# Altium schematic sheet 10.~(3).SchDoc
size 420 x 297 mm
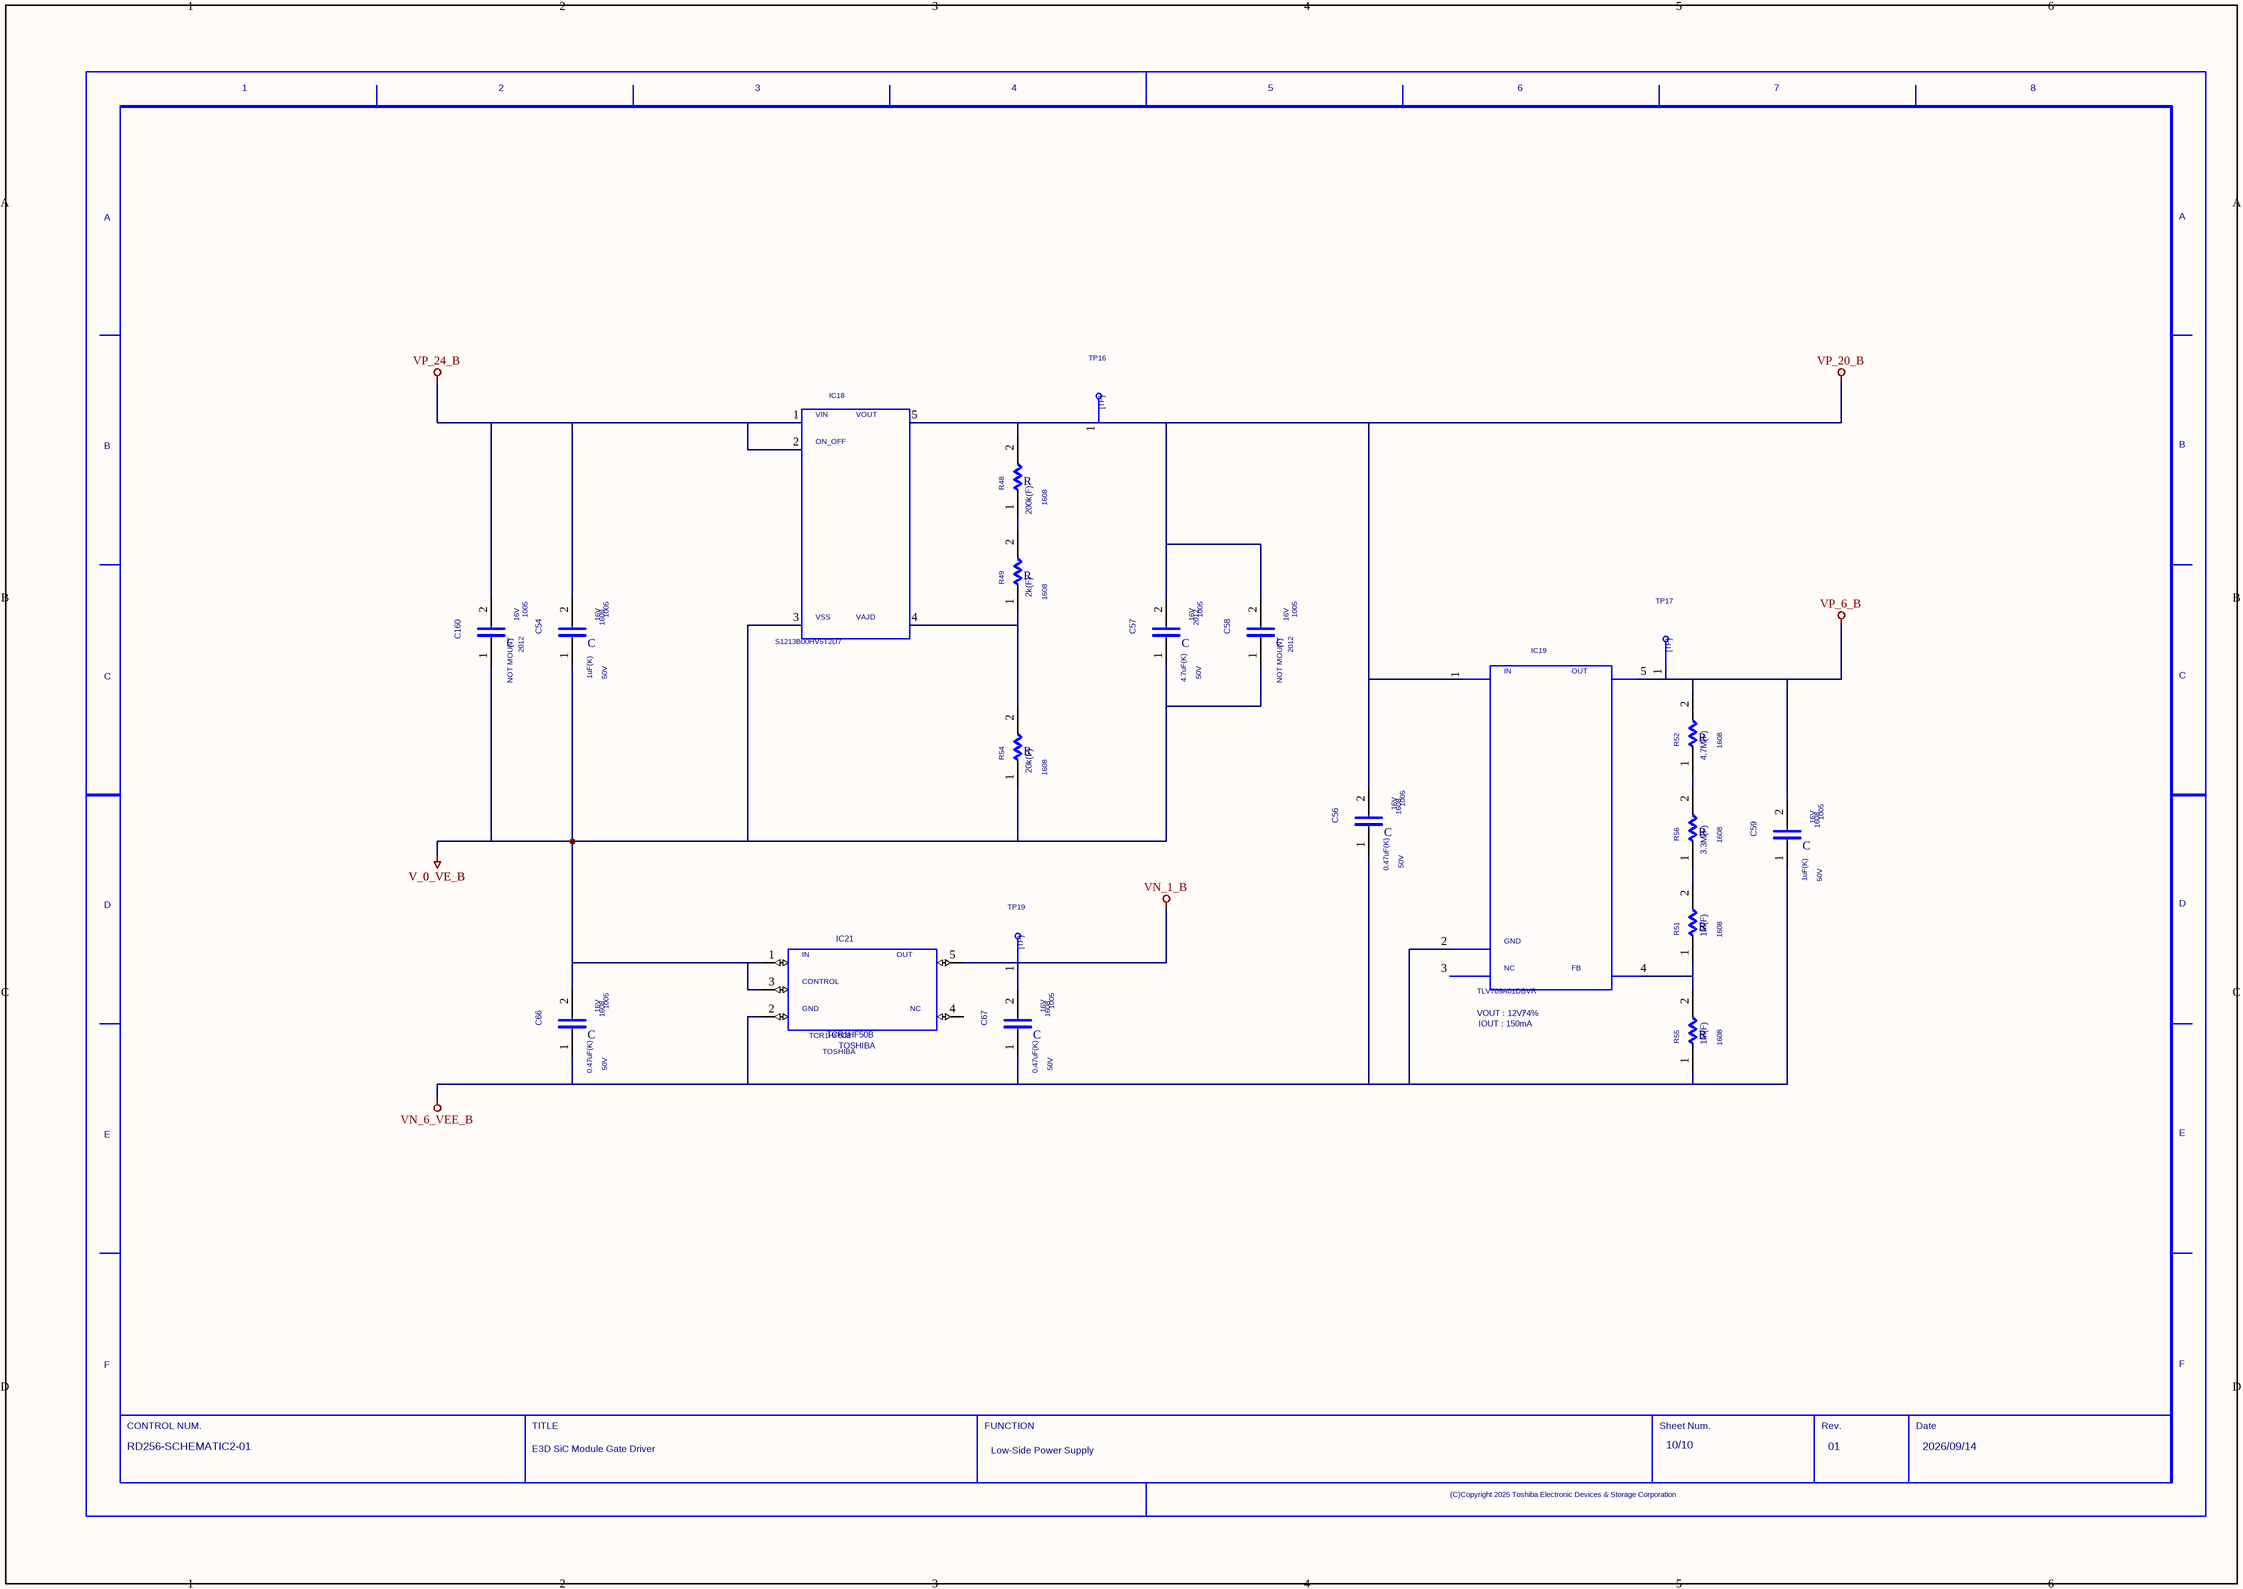
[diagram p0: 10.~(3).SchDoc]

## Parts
C54  VOLTAGE: 16V  CODE: 1005  VAL1: 1uF(K)  VAL2: 50V  SIZECODESMD: 1608  (hidden comment: C)
C56  VOLTAGE: 16V  CODE: 1005  VAL1: 0.47uF(K)  VAL2: 50V  SIZECODESMD: 1608  (hidden comment: C)
C57  VOLTAGE: 16V  CODE: 1005  VAL1: 4.7uF(K)  VAL2: 50V  SIZECODESMD: 2012  (hidden comment: C)
C58  VOLTAGE: 16V  CODE: 1005  SIZECODESMD: 2012  NOTMOUNT: NOT MOUNT  (hidden comment: C)
C59  VOLTAGE: 16V  CODE: 1005  VAL1: 1uF(K)  VAL2: 50V  SIZECODESMD: 1608  (hidden comment: C)
C66  VOLTAGE: 16V  CODE: 1005  VAL1: 0.47uF(K)  VAL2: 50V  SIZECODESMD: 1608  (hidden comment: C)
C67  VOLTAGE: 16V  CODE: 1005  VAL1: 0.47uF(K)  VAL2: 50V  SIZECODESMD: 1608  (hidden comment: C)
C160  VOLTAGE: 16V  CODE: 1005  SIZECODESMD: 2012  NOTMOUNT: NOT MOUNT  (hidden comment: C)
IC18  S1213B00HV5T2U7
IC19  CLASS: IOUT : 150mA  NC: VOUT : 12Vｱ4%  VAL3: TLV709A01DBVR  (hidden comment: TLV709)
IC21  TCR1HF50B  VENDOR: TOSHIBA
R48  VAL1: 200k(F)  SIZECODESMD: 1608  (hidden comment: R)
R49  VAL1: 2k(F)  SIZECODESMD: 1608  (hidden comment: R)
R51  VAL1: 1M(F)  SIZECODESMD: 1608  (hidden comment: R)
R52  VAL1: 4.7M(F)  SIZECODESMD: 1608  (hidden comment: R)
R54  VAL1: 20k(F)  SIZECODESMD: 1608  (hidden comment: R)
R55  VAL1: 1M(F)  SIZECODESMD: 1608  (hidden comment: R)
R56  VAL1: 3.3M(F)  SIZECODESMD: 1608  (hidden comment: R)
TP16  TP  (value not drawn)
TP17  TP  (value not drawn)
TP19  TP  (value not drawn)
U?  REVISION: 01  SHEETNUMBER: 10/10  FUNCTION: Low-Side Power Supply  TITLE: E3D SiC Module Gate Driver  DRAWINGNUMBER: RD256-SCHEMATIC2-01  DATE: 2026/09/14  (hidden comment: WAKU_DEF100)

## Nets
V_0_VE_B: C54.1 C57.1 C58.1 C66.2 C160.1 IC18.3 IC21.1 IC21.3 R54.1
VN_1_B: C67.2 IC21.5 TP19.1
VN_6_VEE_B: C56.1 C59.1 C66.1 C67.1 IC19.2 IC21.2 R55.1
VP_6_B: C59.2 IC19.5 R52.2 TP17.1
VP_20_B: C56.2 C57.2 C58.2 IC18.5 IC19.1 R48.2 TP16.1
VP_24_B: C54.2 C160.2 IC18.1 IC18.2
SIG0101: IC18.4 R49.1 R54.2
SIG0102: R52.1 R56.2
SIG0103: IC19.4 R51.1 R55.2
SIG0104: R48.1 R49.2
SIG0105: R51.2 R56.1

Not connected (* = marked no-connect by the designer): IC19 3; IC21 4

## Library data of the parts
C54 C56-C59 C66 C67 C160 = C: ORIGINALSYMBOLORIGIN: (0,0); VC2: 0; PSPICETEMPLATE: C^@REFDES %1 %2 ?TOLERANCE¦C^@REFDES¦ @VALUE ?IC/IC=@IC/ TC=@TC1,@TC2 ?TOLERANCE¦\n.model C^@REFDES CAP C=1 DEV=@TOLERANCE% TC1=@TC1 TC2=@TC2 VC1=@VC1 VC2=@VC2¦; SAVECOUNT: 2; UPDATETIME: 08:48:12; UPDATEUSER: HP_Z8_KEYSHOT; INSTANCENAME: INS2266227
IC18 = S1213B00HV5T2U7: OriginalSymbolOrigin: (0,0); PSPICETEMPLATE: X^@REFDES %ADJUST %OUTPUT %INPUT @MODEL; SAVECOUNT: 7; UPDATETIME: 09:48:38; UPDATEUSER: t5459927; TIME: 08:48:13; INSTANCENAME: INS2266489
IC19 = TLV709: OriginalSymbolOrigin: (0,0); PSPICETEMPLATE: X^@REFDES %IN %GND %NC %FB %OUT @MODEL; SAVECOUNT: 5; UPDATETIME: 10:01:49; UPDATEUSER: t5459927; TIME: 08:48:16; INSTANCENAME: INS2266385
IC21 = TCR1HF50B: OriginalSymbolOrigin: (-2540,0); PSPICETEMPLATE: X^@REFDES %IN %GND %CONTROL %NC %OUT @MODEL; SAVECOUNT: 4; UPDATETIME: 10:27:35; UPDATEUSER: t5459927; TIME: 11:54:59; INSTANCENAME: INS2266087
R48 R49 R51 R52 R54-R56 = R: ORIGINALSYMBOLORIGIN: (0,0); PSPICETEMPLATE: R^@REFDES %1 %2 ?TOLERANCE¦R^@REFDES¦ @VALUE TC=@TC1,@TC2 ?TOLERANCE¦\n.model R^@REFDES RES R=1 DEV=@TOLERANCE% TC1=@TC1 TC2=@TC2¦; TC2: 0; VAL2: 100mW; SAVECOUNT: 2; UPDATETIME: 08:48:13; UPDATEUSER: HP_Z8_KEYSHOT; INSTANCENAME: INS2266059
TP16 = TP: ORIGINALSYMBOLORIGIN: (0,0); SAVEAREA0: -242,-92,12810,7836; SAVECOUNT: 2; UPDATETIME: 16:18:11; UPDATEUSER: fukuda-y; TIME: 16:12:21; INSTANCENAME: INS2266317
TP17 = TP: ORIGINALSYMBOLORIGIN: (0,0); SAVEAREA0: -242,-92,12810,7836; SAVECOUNT: 2; UPDATETIME: 16:18:11; UPDATEUSER: fukuda-y; TIME: 16:12:21; INSTANCENAME: INS2266305
TP19 = TP: ORIGINALSYMBOLORIGIN: (0,0); SAVEAREA0: -242,-92,12810,7836; SAVECOUNT: 2; UPDATETIME: 16:18:11; UPDATEUSER: fukuda-y; TIME: 16:12:21; INSTANCENAME: INS2266293
U? = WAKU_DEF100: OriginalSymbolOrigin: (10160,284480); SAVECOUNT: 4; UPDATETIME: 11:30:54; UPDATEUSER: t5459927; TIME: 14:30:25; SAVEAREA0: -63393,-16950,474261,314592; PLOTTIME: HH:MM; SHTSAVECOUNT: 18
